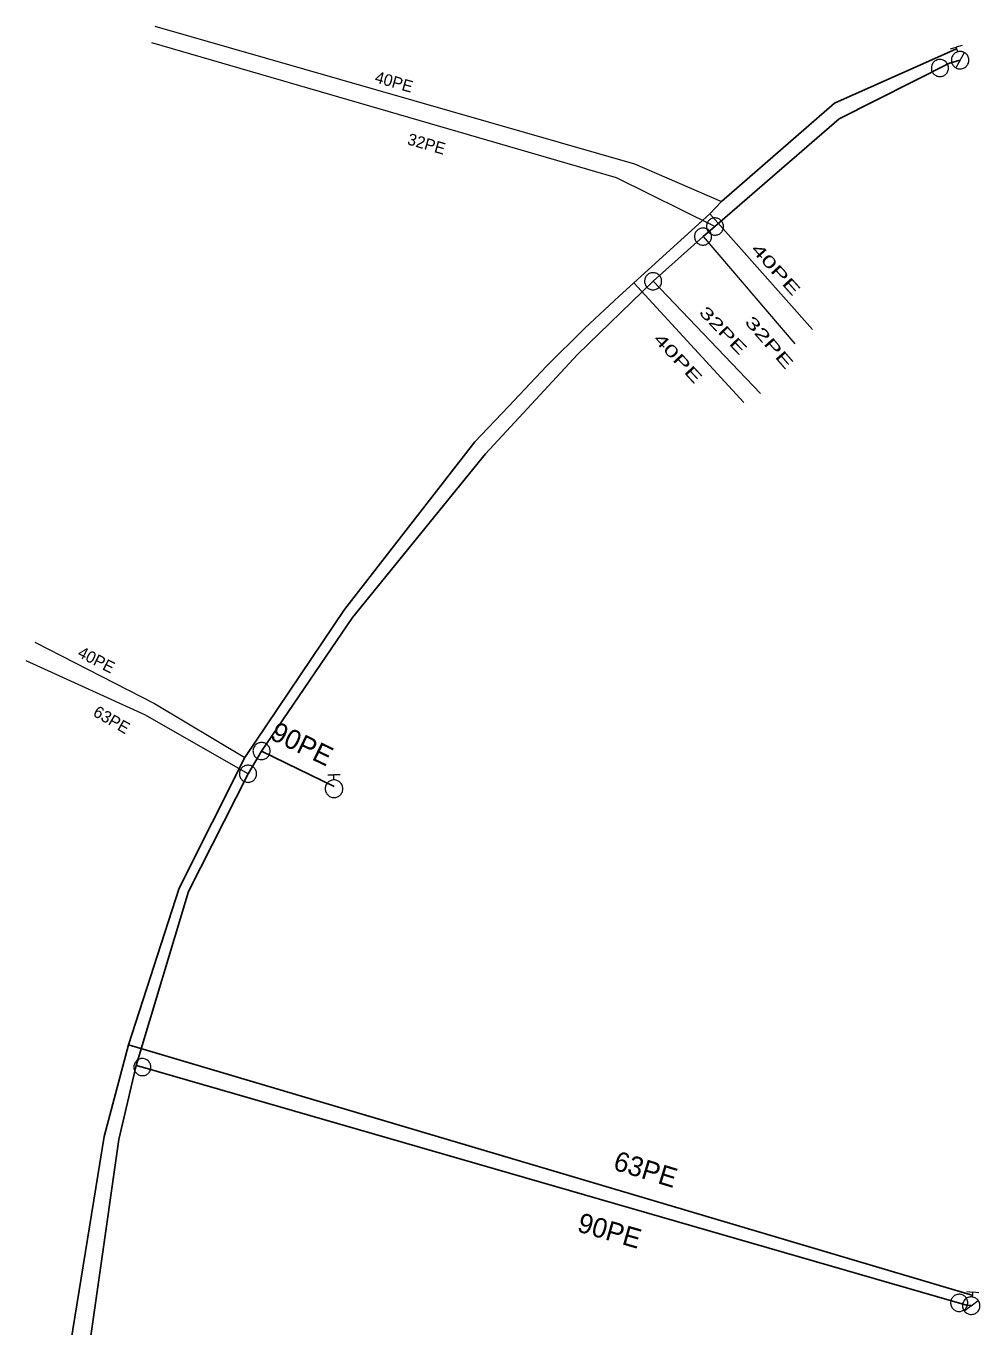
# Model space of a CAD drawing. Extents: x -741806 to -738704, y -1059275 to -1055387.
# Drawn here: x -740310.4 to -740261.8, y -1057135.1 to -1057068.7 of the extents above; entities that cross this region are included whole.
import ezdxf

# ---------------------------------------------------------------- set-up
doc = ezdxf.new("R2010")
doc.units = 0
doc.header["$LTSCALE"] = 0.4
for name, color, linetype, lineweight in [('2', 7, 'Continuous', 25), ('21', 7, 'Continuous', 13), ('50', 7, 'Continuous', 13), ('51', 7, 'Continuous', 13), ('52', 7, 'Continuous', 25), ('56', 7, 'Continuous', 13)]:
    doc.layers.add(name, color=color, linetype=linetype, lineweight=lineweight)
for name, color, linetype in [('5', 7, 'Continuous'), ('53', 7, 'Continuous'), ('54', 7, 'Continuous'), ('55', 7, 'Continuous')]:
    doc.layers.add(name, color=color, linetype=linetype)

msp = doc.modelspace()

# ---------------------------------------------------------------- linework, layer by layer
at = {"layer": '2'}
msp.add_line((-740262.109, -1057133.5), (-740305.219, -1057120.72), dxfattribs=at)
msp.add_lwpolyline([(-740262.96, -1057069.909), (-740269.19, -1057072.669), (-740274.949, -1057077.7), (-740275.559, -1057078.32), (-740280.173, -1057082.526), (-740281.937, -1057084.151), (-740283.887, -1057086.098), (-740285.828, -1057088.145), (-740287.55, -1057089.96), (-740294.199, -1057098.5), (-740299.28, -1057106.06), (-740302.629, -1057112.73), (-740305.219, -1057120.72), (-740306.46, -1057125.389), (-740308.809, -1057139.85), (-740308.96, -1057146.77), (-740308.55, -1057154.01), (-740307.079, -1057159.62), (-740305.57, -1057163.75), (-740300.92, -1057174.76), (-740300.27, -1057176.629), (-740296.46, -1057184.19), (-740290.177, -1057193.486), (-740285.949, -1057197.84)], dxfattribs=at)
at = {"layer": '21'}
for p, q in [((-740275.899, -1057079.48), (-740271.21, -1057084.95)), ((-740278.449, -1057081.76), (-740272.96, -1057087.49))]:
    msp.add_line(p, q, dxfattribs=at)
for points in [[(-740275.289, -1057078.97), (-740280.32, -1057076.49), (-740304.02, -1057069.6)], [(-740299.12, -1057106.889), (-740304.379, -1057103.889), (-740310.449, -1057101.129)]]:
    msp.add_lwpolyline(points, dxfattribs=at)
at = {"layer": '50'}
for p, q in [((-740263.27, -1057069.9), (-740262.974, -1057069.814)), ((-740262.679, -1057069.728), (-740262.974, -1057069.814)), ((-740262.904, -1057070.055), (-740262.974, -1057069.814)), ((-740262.778, -1057070.484), (-740262.563, -1057070.096)), ((-740262.778, -1057070.484), (-740262.994, -1057070.877)), ((-740295.04, -1057106.949), (-740294.732, -1057106.949)), ((-740294.732, -1057107.202), (-740294.732, -1057106.949)), ((-740294.421, -1057106.949), (-740294.732, -1057106.949)), ((-740262.43, -1057133.293), (-740262.124, -1057133.331)), ((-740262.156, -1057133.58), (-740262.124, -1057133.331)), ((-740261.82, -1057133.369), (-740262.124, -1057133.331)), ((-740262.21, -1057134.024), (-740262.564, -1057134.299)), ((-740262.21, -1057134.024), (-740261.859, -1057133.753))]:
    msp.add_line(p, q, dxfattribs=at)
for points in [[(-740262.351, -1057070.364), (-740262.367, -1057070.317), (-740262.385, -1057070.275), (-740262.41, -1057070.234), (-740262.439, -1057070.198), (-740262.468, -1057070.164), (-740262.505, -1057070.133), (-740262.543, -1057070.107), (-740262.585, -1057070.083), (-740262.627, -1057070.064), (-740262.672, -1057070.052), (-740262.717, -1057070.042), (-740262.764, -1057070.036), (-740262.811, -1057070.039), (-740262.857, -1057070.044), (-740262.902, -1057070.054), (-740262.945, -1057070.07), (-740262.987, -1057070.087), (-740263.028, -1057070.113), (-740263.065, -1057070.141), (-740263.101, -1057070.174), (-740263.13, -1057070.208), (-740263.158, -1057070.246), (-740263.18, -1057070.287), (-740263.198, -1057070.329), (-740263.213, -1057070.375), (-740263.223, -1057070.42), (-740263.226, -1057070.466), (-740263.227, -1057070.514), (-740263.219, -1057070.56), (-740263.211, -1057070.606), (-740263.195, -1057070.651), (-740263.175, -1057070.693), (-740263.152, -1057070.731), (-740263.124, -1057070.771), (-740263.091, -1057070.804), (-740263.057, -1057070.836), (-740263.018, -1057070.861), (-740262.978, -1057070.886), (-740262.933, -1057070.904), (-740262.89, -1057070.916), (-740262.842, -1057070.925), (-740262.797, -1057070.929), (-740262.752, -1057070.93), (-740262.702, -1057070.924), (-740262.657, -1057070.914), (-740262.614, -1057070.898), (-740262.572, -1057070.878), (-740262.531, -1057070.854), (-740262.494, -1057070.827), (-740262.459, -1057070.794), (-740262.429, -1057070.76), (-740262.401, -1057070.721), (-740262.379, -1057070.681), (-740262.36, -1057070.639), (-740262.349, -1057070.593), (-740262.337, -1057070.548), (-740262.333, -1057070.501), (-740262.336, -1057070.455), (-740262.341, -1057070.409)], [(-740294.284, -1057107.656), (-740294.285, -1057107.607), (-740294.292, -1057107.562), (-740294.304, -1057107.515), (-740294.319, -1057107.472), (-740294.338, -1057107.43), (-740294.365, -1057107.39), (-740294.397, -1057107.355), (-740294.428, -1057107.319), (-740294.465, -1057107.288), (-740294.506, -1057107.264), (-740294.547, -1057107.242), (-740294.589, -1057107.223), (-740294.635, -1057107.214), (-740294.682, -1057107.205), (-740294.728, -1057107.202), (-740294.773, -1057107.205), (-740294.821, -1057107.209), (-740294.868, -1057107.223), (-740294.91, -1057107.241), (-740294.955, -1057107.261), (-740294.993, -1057107.286), (-740295.031, -1057107.316), (-740295.064, -1057107.35), (-740295.093, -1057107.385), (-740295.12, -1057107.424), (-740295.141, -1057107.465), (-740295.158, -1057107.51), (-740295.174, -1057107.555), (-740295.178, -1057107.602), (-740295.183, -1057107.648), (-740295.181, -1057107.697), (-740295.174, -1057107.744), (-740295.162, -1057107.787), (-740295.146, -1057107.833), (-740295.123, -1057107.874), (-740295.1, -1057107.914), (-740295.068, -1057107.95), (-740295.037, -1057107.984), (-740294.999, -1057108.015), (-740294.961, -1057108.04), (-740294.916, -1057108.062), (-740294.874, -1057108.078), (-740294.83, -1057108.092), (-740294.781, -1057108.1), (-740294.734, -1057108.103), (-740294.687, -1057108.1), (-740294.643, -1057108.092), (-740294.597, -1057108.08), (-740294.552, -1057108.064), (-740294.509, -1057108.042), (-740294.47, -1057108.018), (-740294.433, -1057107.988), (-740294.4, -1057107.956), (-740294.371, -1057107.92), (-740294.346, -1057107.879), (-740294.32, -1057107.838), (-740294.305, -1057107.795), (-740294.293, -1057107.748), (-740294.285, -1057107.703)], [(-740261.77, -1057134.083), (-740261.767, -1057134.034), (-740261.766, -1057133.988), (-740261.773, -1057133.94), (-740261.785, -1057133.896), (-740261.799, -1057133.854), (-740261.82, -1057133.81), (-740261.845, -1057133.771), (-740261.873, -1057133.732), (-740261.904, -1057133.698), (-740261.941, -1057133.67), (-740261.979, -1057133.643), (-740262.019, -1057133.618), (-740262.064, -1057133.603), (-740262.108, -1057133.589), (-740262.154, -1057133.581), (-740262.2, -1057133.578), (-740262.245, -1057133.577), (-740262.292, -1057133.584), (-740262.338, -1057133.596), (-740262.383, -1057133.611), (-740262.424, -1057133.631), (-740262.464, -1057133.656), (-740262.501, -1057133.684), (-740262.534, -1057133.715), (-740262.566, -1057133.752), (-740262.593, -1057133.79), (-740262.614, -1057133.83), (-740262.634, -1057133.874), (-740262.644, -1057133.919), (-740262.656, -1057133.964), (-740262.659, -1057134.012), (-740262.657, -1057134.059), (-740262.651, -1057134.103), (-740262.641, -1057134.15), (-740262.624, -1057134.194), (-740262.605, -1057134.237), (-740262.58, -1057134.275), (-740262.553, -1057134.314), (-740262.519, -1057134.348), (-740262.484, -1057134.377), (-740262.444, -1057134.404), (-740262.403, -1057134.425), (-740262.362, -1057134.444), (-740262.315, -1057134.458), (-740262.269, -1057134.467), (-740262.223, -1057134.47), (-740262.177, -1057134.468), (-740262.13, -1057134.462), (-740262.085, -1057134.452), (-740262.04, -1057134.435), (-740261.999, -1057134.416), (-740261.958, -1057134.391), (-740261.922, -1057134.363), (-740261.888, -1057134.332), (-740261.859, -1057134.295), (-740261.83, -1057134.258), (-740261.808, -1057134.216), (-740261.792, -1057134.173), (-740261.779, -1057134.128)]]:
    msp.add_lwpolyline(points, close=True, dxfattribs=at)
at = {"layer": '51'}
for points in [[(-740263.419, -1057070.685), (-740263.441, -1057070.646), (-740263.468, -1057070.609), (-740263.499, -1057070.574), (-740263.532, -1057070.544), (-740263.569, -1057070.516), (-740263.609, -1057070.493), (-740263.651, -1057070.475), (-740263.694, -1057070.46), (-740263.739, -1057070.451), (-740263.784, -1057070.446), (-740263.83, -1057070.446), (-740263.876, -1057070.45), (-740263.921, -1057070.459), (-740263.964, -1057070.473), (-740264.006, -1057070.492), (-740264.047, -1057070.514), (-740264.084, -1057070.541), (-740264.117, -1057070.572), (-740264.148, -1057070.606), (-740264.175, -1057070.643), (-740264.198, -1057070.683), (-740264.217, -1057070.724), (-740264.231, -1057070.768), (-740264.241, -1057070.812), (-740264.246, -1057070.858), (-740264.246, -1057070.904), (-740264.241, -1057070.949), (-740264.232, -1057070.995), (-740264.218, -1057071.038), (-740264.2, -1057071.08), (-740264.177, -1057071.119), (-740264.15, -1057071.156), (-740264.119, -1057071.191), (-740264.086, -1057071.221), (-740264.049, -1057071.248), (-740264.009, -1057071.272), (-740263.967, -1057071.29), (-740263.924, -1057071.305), (-740263.879, -1057071.314), (-740263.834, -1057071.319), (-740263.788, -1057071.319), (-740263.742, -1057071.315), (-740263.697, -1057071.305), (-740263.654, -1057071.292), (-740263.612, -1057071.273), (-740263.572, -1057071.25), (-740263.535, -1057071.223), (-740263.501, -1057071.193), (-740263.47, -1057071.159), (-740263.443, -1057071.121), (-740263.42, -1057071.082), (-740263.401, -1057071.041), (-740263.387, -1057070.997), (-740263.377, -1057070.953), (-740263.372, -1057070.906), (-740263.372, -1057070.86), (-740263.377, -1057070.816), (-740263.386, -1057070.77), (-740263.4, -1057070.727), (-740263.419, -1057070.686)], [(-740274.953, -1057078.69), (-740274.983, -1057078.656), (-740275.018, -1057078.626), (-740275.056, -1057078.599), (-740275.095, -1057078.578), (-740275.137, -1057078.56), (-740275.181, -1057078.546), (-740275.226, -1057078.537), (-740275.272, -1057078.533), (-740275.317, -1057078.534), (-740275.363, -1057078.539), (-740275.408, -1057078.55), (-740275.451, -1057078.564), (-740275.493, -1057078.583), (-740275.532, -1057078.607), (-740275.568, -1057078.635), (-740275.602, -1057078.666), (-740275.633, -1057078.7), (-740275.659, -1057078.737), (-740275.681, -1057078.778), (-740275.699, -1057078.82), (-740275.712, -1057078.864), (-740275.721, -1057078.908), (-740275.725, -1057078.954), (-740275.725, -1057079), (-740275.719, -1057079.046), (-740275.709, -1057079.091), (-740275.694, -1057079.133), (-740275.674, -1057079.175), (-740275.651, -1057079.214), (-740275.624, -1057079.252), (-740275.592, -1057079.284), (-740275.558, -1057079.314), (-740275.52, -1057079.341), (-740275.481, -1057079.363), (-740275.438, -1057079.381), (-740275.394, -1057079.395), (-740275.35, -1057079.403), (-740275.304, -1057079.408), (-740275.258, -1057079.406), (-740275.213, -1057079.401), (-740275.168, -1057079.391), (-740275.124, -1057079.376), (-740275.083, -1057079.357), (-740275.044, -1057079.334), (-740275.007, -1057079.306), (-740274.973, -1057079.275), (-740274.944, -1057079.24), (-740274.917, -1057079.203), (-740274.895, -1057079.163), (-740274.877, -1057079.12), (-740274.864, -1057079.077), (-740274.854, -1057079.032), (-740274.851, -1057078.986), (-740274.851, -1057078.941), (-740274.857, -1057078.895), (-740274.867, -1057078.85), (-740274.882, -1057078.807), (-740274.901, -1057078.765), (-740274.925, -1057078.726), (-740274.952, -1057078.69)], [(-740298.206, -1057105.354), (-740298.245, -1057105.333), (-740298.288, -1057105.316), (-740298.332, -1057105.303), (-740298.377, -1057105.295), (-740298.423, -1057105.293), (-740298.469, -1057105.294), (-740298.514, -1057105.301), (-740298.559, -1057105.312), (-740298.601, -1057105.328), (-740298.642, -1057105.348), (-740298.681, -1057105.373), (-740298.718, -1057105.401), (-740298.75, -1057105.433), (-740298.779, -1057105.468), (-740298.805, -1057105.506), (-740298.826, -1057105.547), (-740298.843, -1057105.589), (-740298.856, -1057105.633), (-740298.863, -1057105.679), (-740298.866, -1057105.725), (-740298.864, -1057105.77), (-740298.858, -1057105.815), (-740298.846, -1057105.86), (-740298.831, -1057105.903), (-740298.81, -1057105.944), (-740298.786, -1057105.983), (-740298.758, -1057106.018), (-740298.725, -1057106.052), (-740298.69, -1057106.081), (-740298.652, -1057106.107), (-740298.612, -1057106.127), (-740298.57, -1057106.144), (-740298.525, -1057106.157), (-740298.481, -1057106.165), (-740298.435, -1057106.167), (-740298.388, -1057106.166), (-740298.343, -1057106.159), (-740298.299, -1057106.148), (-740298.256, -1057106.132), (-740298.215, -1057106.112), (-740298.176, -1057106.087), (-740298.14, -1057106.059), (-740298.108, -1057106.027), (-740298.078, -1057105.992), (-740298.053, -1057105.954), (-740298.031, -1057105.913), (-740298.015, -1057105.87), (-740298.002, -1057105.827), (-740297.994, -1057105.781), (-740297.991, -1057105.735), (-740297.993, -1057105.69), (-740297.999, -1057105.645), (-740298.011, -1057105.6), (-740298.026, -1057105.557), (-740298.047, -1057105.516), (-740298.072, -1057105.477), (-740298.1, -1057105.442), (-740298.132, -1057105.408), (-740298.167, -1057105.379), (-740298.205, -1057105.355)], [(-740299.499, -1057106.672), (-740299.519, -1057106.712), (-740299.536, -1057106.754), (-740299.547, -1057106.799), (-740299.554, -1057106.844), (-740299.556, -1057106.89), (-740299.554, -1057106.936), (-740299.546, -1057106.981), (-740299.535, -1057107.025), (-740299.517, -1057107.067), (-740299.497, -1057107.108), (-740299.472, -1057107.146), (-740299.443, -1057107.183), (-740299.41, -1057107.215), (-740299.375, -1057107.243), (-740299.336, -1057107.268), (-740299.295, -1057107.289), (-740299.252, -1057107.305), (-740299.208, -1057107.316), (-740299.162, -1057107.323), (-740299.116, -1057107.325), (-740299.071, -1057107.322), (-740299.026, -1057107.316), (-740298.982, -1057107.303), (-740298.939, -1057107.287), (-740298.898, -1057107.265), (-740298.859, -1057107.24), (-740298.825, -1057107.211), (-740298.792, -1057107.178), (-740298.764, -1057107.143), (-740298.738, -1057107.104), (-740298.719, -1057107.064), (-740298.702, -1057107.021), (-740298.691, -1057106.976), (-740298.684, -1057106.932), (-740298.682, -1057106.886), (-740298.684, -1057106.839), (-740298.692, -1057106.795), (-740298.703, -1057106.75), (-740298.721, -1057106.708), (-740298.741, -1057106.667), (-740298.766, -1057106.629), (-740298.795, -1057106.593), (-740298.828, -1057106.561), (-740298.863, -1057106.532), (-740298.902, -1057106.508), (-740298.943, -1057106.487), (-740298.986, -1057106.471), (-740299.03, -1057106.459), (-740299.076, -1057106.452), (-740299.122, -1057106.45), (-740299.167, -1057106.453), (-740299.212, -1057106.46), (-740299.256, -1057106.473), (-740299.299, -1057106.489), (-740299.34, -1057106.51), (-740299.379, -1057106.535), (-740299.413, -1057106.564), (-740299.446, -1057106.597), (-740299.474, -1057106.633), (-740299.498, -1057106.671)], [(-740304.086, -1057121.959), (-740304.077, -1057121.915), (-740304.073, -1057121.87), (-740304.073, -1057121.823), (-740304.078, -1057121.779), (-740304.088, -1057121.734), (-740304.103, -1057121.69), (-740304.122, -1057121.648), (-740304.145, -1057121.609), (-740304.173, -1057121.572), (-740304.203, -1057121.539), (-740304.238, -1057121.508), (-740304.275, -1057121.481), (-740304.315, -1057121.458), (-740304.356, -1057121.44), (-740304.4, -1057121.427), (-740304.445, -1057121.417), (-740304.491, -1057121.413), (-740304.536, -1057121.413), (-740304.582, -1057121.419), (-740304.627, -1057121.429), (-740304.67, -1057121.444), (-740304.712, -1057121.462), (-740304.751, -1057121.486), (-740304.788, -1057121.513), (-740304.822, -1057121.544), (-740304.853, -1057121.579), (-740304.879, -1057121.615), (-740304.902, -1057121.656), (-740304.92, -1057121.698), (-740304.934, -1057121.742), (-740304.942, -1057121.786), (-740304.947, -1057121.831), (-740304.946, -1057121.878), (-740304.941, -1057121.922), (-740304.931, -1057121.967), (-740304.917, -1057122.011), (-740304.898, -1057122.052), (-740304.875, -1057122.092), (-740304.847, -1057122.129), (-740304.816, -1057122.162), (-740304.782, -1057122.193), (-740304.745, -1057122.22), (-740304.705, -1057122.242), (-740304.663, -1057122.261), (-740304.619, -1057122.274), (-740304.574, -1057122.284), (-740304.528, -1057122.287), (-740304.483, -1057122.287), (-740304.437, -1057122.282), (-740304.392, -1057122.272), (-740304.349, -1057122.257), (-740304.307, -1057122.239), (-740304.268, -1057122.215), (-740304.231, -1057122.188), (-740304.197, -1057122.157), (-740304.167, -1057122.122), (-740304.141, -1057122.086), (-740304.118, -1057122.045), (-740304.1, -1057122.003), (-740304.087, -1057121.96)], [(-740262.408, -1057134.001), (-740262.397, -1057133.957), (-740262.391, -1057133.912), (-740262.391, -1057133.866), (-740262.394, -1057133.821), (-740262.403, -1057133.776), (-740262.416, -1057133.731), (-740262.434, -1057133.69), (-740262.456, -1057133.649), (-740262.483, -1057133.612), (-740262.512, -1057133.578), (-740262.546, -1057133.546), (-740262.583, -1057133.518), (-740262.622, -1057133.494), (-740262.663, -1057133.475), (-740262.706, -1057133.46), (-740262.751, -1057133.449), (-740262.796, -1057133.444), (-740262.842, -1057133.443), (-740262.888, -1057133.447), (-740262.933, -1057133.456), (-740262.977, -1057133.47), (-740263.019, -1057133.486), (-740263.059, -1057133.509), (-740263.096, -1057133.535), (-740263.131, -1057133.565), (-740263.163, -1057133.599), (-740263.19, -1057133.635), (-740263.214, -1057133.675), (-740263.233, -1057133.716), (-740263.249, -1057133.759), (-740263.258, -1057133.804), (-740263.264, -1057133.849), (-740263.265, -1057133.895), (-740263.261, -1057133.94), (-740263.253, -1057133.985), (-740263.239, -1057134.03), (-740263.221, -1057134.071), (-740263.2, -1057134.112), (-740263.173, -1057134.149), (-740263.143, -1057134.183), (-740263.11, -1057134.215), (-740263.073, -1057134.243), (-740263.034, -1057134.266), (-740262.993, -1057134.286), (-740262.949, -1057134.301), (-740262.904, -1057134.312), (-740262.859, -1057134.316), (-740262.814, -1057134.318), (-740262.768, -1057134.314), (-740262.722, -1057134.305), (-740262.679, -1057134.291), (-740262.637, -1057134.274), (-740262.597, -1057134.252), (-740262.559, -1057134.226), (-740262.524, -1057134.195), (-740262.493, -1057134.162), (-740262.466, -1057134.126), (-740262.442, -1057134.086), (-740262.422, -1057134.045), (-740262.408, -1057134.002)]]:
    msp.add_lwpolyline(points, dxfattribs=at)
for points in [[(-740275.572, -1057079.189), (-740275.604, -1057079.156), (-740275.639, -1057079.128), (-740275.678, -1057079.102), (-740275.718, -1057079.081), (-740275.761, -1057079.065), (-740275.806, -1057079.052), (-740275.851, -1057079.046), (-740275.896, -1057079.042), (-740275.942, -1057079.045), (-740275.987, -1057079.052), (-740276.031, -1057079.064), (-740276.075, -1057079.08), (-740276.116, -1057079.1), (-740276.154, -1057079.125), (-740276.189, -1057079.154), (-740276.222, -1057079.186), (-740276.251, -1057079.221), (-740276.276, -1057079.26), (-740276.297, -1057079.301), (-740276.313, -1057079.344), (-740276.325, -1057079.388), (-740276.333, -1057079.433), (-740276.335, -1057079.479), (-740276.333, -1057079.524), (-740276.326, -1057079.57), (-740276.314, -1057079.615), (-740276.298, -1057079.657), (-740276.277, -1057079.698), (-740276.252, -1057079.736), (-740276.224, -1057079.773), (-740276.192, -1057079.804), (-740276.157, -1057079.833), (-740276.118, -1057079.859), (-740276.078, -1057079.879), (-740276.035, -1057079.896), (-740275.99, -1057079.908), (-740275.945, -1057079.915), (-740275.899, -1057079.918), (-740275.854, -1057079.915), (-740275.809, -1057079.908), (-740275.764, -1057079.897), (-740275.721, -1057079.881), (-740275.681, -1057079.86), (-740275.642, -1057079.836), (-740275.606, -1057079.806), (-740275.573, -1057079.774), (-740275.545, -1057079.738), (-740275.52, -1057079.701), (-740275.499, -1057079.659), (-740275.482, -1057079.616), (-740275.471, -1057079.572), (-740275.462, -1057079.528), (-740275.461, -1057079.482), (-740275.462, -1057079.436), (-740275.47, -1057079.391), (-740275.481, -1057079.346), (-740275.497, -1057079.304), (-740275.518, -1057079.262), (-740275.543, -1057079.224)], [(-740278.134, -1057081.456), (-740278.167, -1057081.425), (-740278.203, -1057081.397), (-740278.243, -1057081.373), (-740278.284, -1057081.354), (-740278.328, -1057081.34), (-740278.373, -1057081.329), (-740278.418, -1057081.324), (-740278.464, -1057081.323), (-740278.509, -1057081.328), (-740278.554, -1057081.336), (-740278.598, -1057081.349), (-740278.641, -1057081.367), (-740278.681, -1057081.389), (-740278.718, -1057081.415), (-740278.752, -1057081.446), (-740278.784, -1057081.479), (-740278.811, -1057081.516), (-740278.835, -1057081.555), (-740278.854, -1057081.597), (-740278.868, -1057081.641), (-740278.878, -1057081.685), (-740278.885, -1057081.73), (-740278.885, -1057081.776), (-740278.881, -1057081.822), (-740278.872, -1057081.867), (-740278.859, -1057081.911), (-740278.841, -1057081.952), (-740278.818, -1057081.993), (-740278.792, -1057082.03), (-740278.762, -1057082.065), (-740278.729, -1057082.096), (-740278.692, -1057082.123), (-740278.652, -1057082.147), (-740278.612, -1057082.166), (-740278.568, -1057082.181), (-740278.523, -1057082.191), (-740278.478, -1057082.196), (-740278.432, -1057082.198), (-740278.386, -1057082.193), (-740278.342, -1057082.184), (-740278.298, -1057082.171), (-740278.255, -1057082.153), (-740278.216, -1057082.131), (-740278.178, -1057082.105), (-740278.143, -1057082.074), (-740278.112, -1057082.041), (-740278.085, -1057082.004), (-740278.061, -1057081.965), (-740278.042, -1057081.923), (-740278.027, -1057081.88), (-740278.017, -1057081.835), (-740278.011, -1057081.79), (-740278.011, -1057081.744), (-740278.014, -1057081.699), (-740278.024, -1057081.653), (-740278.037, -1057081.609), (-740278.055, -1057081.568), (-740278.077, -1057081.527), (-740278.104, -1057081.49)]]:
    msp.add_lwpolyline(points, close=True, dxfattribs=at)
at = {"layer": '52'}
msp.add_line((-740298.43, -1057105.73), (-740294.719, -1057107.54), dxfattribs=at)
for points in [[(-740283.129, -1057198.97), (-740283.26, -1057198.81), (-740289.74, -1057192.772), (-740295.66, -1057184.32), (-740299.64, -1057176.48), (-740305.079, -1057163.11), (-740306.469, -1057159.919), (-740308.03, -1057153.929), (-740308.37, -1057146.06), (-740307.77, -1057139.98), (-740305.71, -1057125.55), (-740304.82, -1057121.77), (-740302.16, -1057112.889), (-740299.12, -1057106.889), (-740298.43, -1057105.73), (-740293.78, -1057098.919), (-740287, -1057090.56), (-740282.309, -1057085.5), (-740278.449, -1057081.76), (-740275.899, -1057079.48), (-740275.289, -1057078.97), (-740268.949, -1057073.48), (-740263.329, -1057070.639), (-740262.78, -1057070.48)], [(-740304.82, -1057121.77), (-740304.51, -1057121.85), (-740262.449, -1057133.99), (-740262.21, -1057134.02)]]:
    msp.add_lwpolyline(points, dxfattribs=at)
at = {"layer": '56'}
for p, q in [((-740270.309, -1057084.22), (-740275.559, -1057078.32)), ((-740273.82, -1057087.95), (-740279.43, -1057081.848))]:
    msp.add_line(p, q, dxfattribs=at)
for points in [[(-740303.87, -1057068.74), (-740279.39, -1057075.77), (-740274.949, -1057077.7)], [(-740310, -1057100.169), (-740303.899, -1057103.31), (-740299.28, -1057106.06)]]:
    msp.add_lwpolyline(points, dxfattribs=at)

# ---------------------------------------------------------------- texts
at = {"layer": '5'}
msp.add_text('63PE', height=1, rotation=343, dxfattribs=at).set_placement((-740280.536, -1057127.068))
at = {"layer": '53'}
for rotation, p in [(334, (-740298.049, -1057105.096)), (344, (-740282.373, -1057130.224))]:
    msp.add_text('90PE', height=1, rotation=rotation, dxfattribs=at).set_placement(p)
at = {"layer": '54'}
for s, rotation, p in [('32PE', 344, (-740291.032, -1057074.77)), ('63PE', 330, (-740307.075, -1057103.902))]:
    msp.add_text(s, height=0.6, rotation=rotation, dxfattribs=at).set_placement(p)
for rotation, width, p in [(314, 1.55, (-740276.143, -1057083.384)), (311, 1.65, (-740273.808, -1057083.855))]:
    msp.add_text('32PE', height=0.6, rotation=rotation, dxfattribs=dict(at, width=width)).set_placement(p)
at = {"layer": '55'}
for rotation, p in [(344, (-740292.691, -1057071.605)), (333, (-740307.865, -1057100.896))]:
    msp.add_text('40PE', height=0.6, rotation=rotation, dxfattribs=at).set_placement(p)
for rotation, width, p in [(312, 1.65, (-740273.484, -1057080.152)), (313, 1.6, (-740278.463, -1057084.743))]:
    msp.add_text('40PE', height=0.6, rotation=rotation, dxfattribs=dict(at, width=width)).set_placement(p)

doc.saveas('drawing.dxf')
